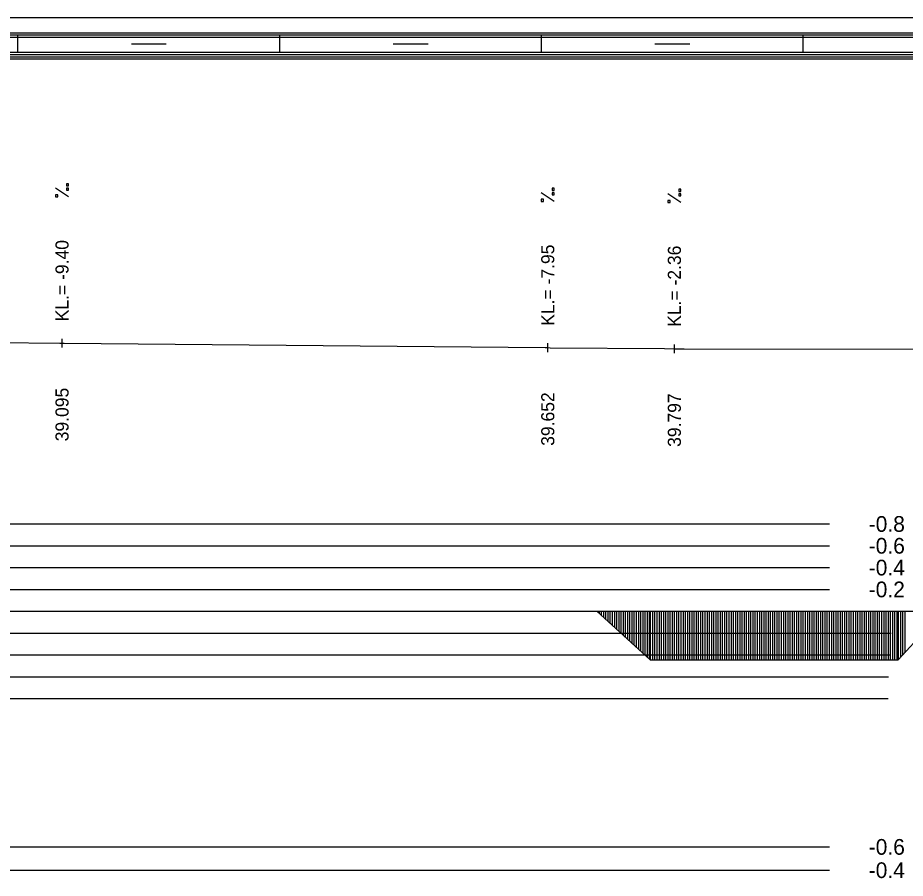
# Model space of a CAD drawing. Extents: x 2 to 10148, y 0 to 380.
# Drawn here: x 4205 to 4306.7, y 281.4 to 380 of the extents above; entities that cross this region are included whole.
import ezdxf

# ---------------------------------------------------------------- set-up
doc = ezdxf.new("R2010")
doc.units = 0
for name, color, linetype in [('NIVELETA_CARA', 7, 'Continuous'), ('NIVELETA_TEXT', 7, 'Continuous'), ('RAM', 7, 'Continuous'), ('ZRYCHL_CARA_C', 7, 'Continuous'), ('ZRYCHL_RASTR', 7, 'Continuous'), ('ZRYCHL_TEXT', 7, 'Continuous')]:
    doc.layers.add(name, color=color, linetype=linetype)

msp = doc.modelspace()

# ---------------------------------------------------------------- linework, layer by layer
at = {"layer": 'NIVELETA_CARA'}
for p, q in [((4188.22, 342.95), (4209.81, 342.72)), ((4210.05, 342.22), (4210.05, 343.22)), ((4209.81, 342.72), (4210.05, 342.72)), ((4210.05, 342.72), (4210.3, 342.72)), ((4210.3, 342.72), (4265.43, 342.2)), ((4265.43, 342.2), (4265.72, 342.2)), ((4265.72, 341.7), (4265.72, 342.7)), ((4265.72, 342.2), (4266.01, 342.19)), ((4266.01, 342.19), (4279.11, 342.09)), ((4279.11, 342.09), (4280.23, 342.08)), ((4280.23, 341.58), (4280.23, 342.58)), ((4280.23, 342.08), (4281.35, 342.08)), ((4281.35, 342.08), (4311.18, 342.01))]:
    msp.add_line(p, q, dxfattribs=at)
at = {"layer": 'NIVELETA_TEXT'}
for p, q in [((4210.8, 359.47), (4209.31, 360.46)), ((4210.8, 360.99), (4210.55, 360.99)), ((4210.55, 360.99), (4210.55, 360.74)), ((4210.55, 360.74), (4210.8, 360.74)), ((4210.55, 360.74), (4210.56, 360.74)), ((4210.8, 360.48), (4210.55, 360.48)), ((4210.55, 360.48), (4210.55, 360.23)), ((4210.55, 360.23), (4210.8, 360.23)), ((4210.55, 360.23), (4210.56, 360.23)), ((4210.8, 360.74), (4210.8, 360.99)), ((4210.8, 360.23), (4210.8, 360.48)), ((4266.47, 360.46), (4266.22, 360.46)), ((4266.22, 360.46), (4266.22, 360.22)), ((4266.22, 360.22), (4266.47, 360.22)), ((4266.22, 360.22), (4266.23, 360.22)), ((4266.47, 360.22), (4266.47, 360.46)), ((4280.98, 360.35), (4280.73, 360.35)), ((4280.73, 360.35), (4280.73, 360.11)), ((4280.73, 360.11), (4280.74, 360.1)), ((4280.73, 360.1), (4280.98, 360.1)), ((4280.98, 360.1), (4280.98, 360.35)), ((4209.55, 359.72), (4209.31, 359.72)), ((4209.31, 359.72), (4209.31, 359.48)), ((4209.31, 359.48), (4209.31, 359.47)), ((4209.31, 359.47), (4209.55, 359.47)), ((4209.55, 359.47), (4209.55, 359.72)), ((4266.47, 358.95), (4264.97, 359.94)), ((4265.22, 359.2), (4264.97, 359.2)), ((4264.97, 359.2), (4264.97, 358.95)), ((4265.22, 358.95), (4265.22, 359.2)), ((4266.47, 359.95), (4266.22, 359.95)), ((4266.22, 359.95), (4266.22, 359.71)), ((4266.22, 359.71), (4266.23, 359.7)), ((4266.22, 359.7), (4266.47, 359.7)), ((4266.47, 359.7), (4266.47, 359.95)), ((4280.98, 358.83), (4279.48, 359.82)), ((4279.73, 359.08), (4279.48, 359.08)), ((4279.48, 359.08), (4279.48, 358.84)), ((4279.73, 358.83), (4279.73, 359.08)), ((4280.98, 359.84), (4280.73, 359.84)), ((4280.73, 359.84), (4280.73, 359.59)), ((4280.73, 359.59), (4280.98, 359.59)), ((4280.73, 359.59), (4280.74, 359.59)), ((4280.98, 359.59), (4280.98, 359.84)), ((4264.97, 358.95), (4265.22, 358.95)), ((4264.97, 358.95), (4264.98, 358.95)), ((4279.48, 358.84), (4279.49, 358.83)), ((4279.48, 358.83), (4279.73, 358.83))]:
    msp.add_line(p, q, dxfattribs=at)
at = {"layer": 'RAM'}
for p, q in [((5128.6, 380), (4045.76, 380)), ((5128.6, 378.25), (4045.76, 378.25)), ((5128.6, 378), (4045.76, 378)), ((5128.6, 377.75), (4045.76, 377.75)), ((4205, 376), (4205, 378)), ((4235, 376), (4235, 378)), ((4265, 376), (4265, 378)), ((4295, 376), (4295, 378)), ((4218, 377), (4222, 377)), ((4248, 377), (4252, 377)), ((4278, 377), (4282, 377)), ((5128.6, 376), (4045.76, 376)), ((5128.6, 375.75), (4045.76, 375.75)), ((5128.6, 375.5), (4045.76, 375.5)), ((5128.6, 375.25), (4045.76, 375.25))]:
    msp.add_line(p, q, dxfattribs=at)
at = {"layer": 'ZRYCHL_CARA_C'}
for p, q in [((4045.76, 312), (5128.6, 312)), ((4271.35, 312), (4277.47, 306.42)), ((4271.6, 312), (4271.6, 311.77)), ((4271.85, 312), (4271.85, 311.54)), ((4272.1, 312), (4272.1, 311.32)), ((4272.35, 312), (4272.35, 311.09)), ((4272.6, 312), (4272.6, 310.86)), ((4272.85, 312), (4272.85, 310.63)), ((4273.1, 312), (4273.1, 310.4)), ((4273.35, 312), (4273.35, 310.18)), ((4273.6, 312), (4273.6, 309.95)), ((4273.85, 312), (4273.85, 309.72)), ((4274.1, 312), (4274.1, 309.49)), ((4274.35, 312), (4274.35, 309.26)), ((4274.6, 312), (4274.6, 309.04)), ((4274.85, 312), (4274.85, 308.81)), ((4275.1, 312), (4275.1, 308.58)), ((4275.35, 312), (4275.35, 308.35)), ((4275.6, 312), (4275.6, 308.13)), ((4275.85, 312), (4275.85, 307.9)), ((4276.1, 312), (4276.1, 307.67)), ((4276.35, 312), (4276.35, 307.44)), ((4276.6, 312), (4276.6, 307.21)), ((4276.85, 312), (4276.85, 306.99)), ((4277.1, 312), (4277.1, 306.76)), ((4277.35, 312), (4277.35, 306.53)), ((4277.47, 312), (4277.47, 306.42)), ((4277.72, 312), (4277.72, 306.42)), ((4277.97, 312), (4277.97, 306.42)), ((4278.22, 312), (4278.22, 306.42)), ((4278.47, 312), (4278.47, 306.42)), ((4278.72, 312), (4278.72, 306.42)), ((4278.97, 312), (4278.97, 306.42)), ((4279.22, 312), (4279.22, 306.42)), ((4279.47, 312), (4279.47, 306.42)), ((4279.72, 312), (4279.72, 306.42)), ((4279.97, 312), (4279.97, 306.42)), ((4280.22, 312), (4280.22, 306.42)), ((4280.47, 312), (4280.47, 306.42)), ((4280.72, 312), (4280.72, 306.42)), ((4280.97, 312), (4280.97, 306.42)), ((4281.22, 312), (4281.22, 306.42)), ((4281.47, 312), (4281.47, 306.42)), ((4281.72, 312), (4281.72, 306.42)), ((4281.97, 312), (4281.97, 306.42)), ((4282.22, 312), (4282.22, 306.42)), ((4282.47, 312), (4282.47, 306.42)), ((4282.72, 312), (4282.72, 306.42)), ((4282.97, 312), (4282.97, 306.42)), ((4283.22, 312), (4283.22, 306.42)), ((4283.47, 312), (4283.47, 306.42)), ((4283.72, 312), (4283.72, 306.42)), ((4283.97, 312), (4283.97, 306.42)), ((4284.22, 312), (4284.22, 306.42)), ((4284.47, 312), (4284.47, 306.42)), ((4284.72, 312), (4284.72, 306.42)), ((4284.97, 312), (4284.97, 306.42)), ((4285.22, 312), (4285.22, 306.42)), ((4285.47, 312), (4285.47, 306.42)), ((4285.72, 312), (4285.72, 306.42)), ((4285.97, 312), (4285.97, 306.42)), ((4286.22, 312), (4286.22, 306.42)), ((4286.47, 312), (4286.47, 306.42)), ((4286.72, 312), (4286.72, 306.42)), ((4286.97, 312), (4286.97, 306.42)), ((4287.22, 312), (4287.22, 306.42)), ((4287.47, 312), (4287.47, 306.42)), ((4287.72, 312), (4287.72, 306.42)), ((4287.97, 312), (4287.97, 306.42)), ((4288.22, 312), (4288.22, 306.42)), ((4288.47, 312), (4288.47, 306.42)), ((4288.72, 312), (4288.72, 306.42)), ((4288.97, 312), (4288.97, 306.42)), ((4289.22, 312), (4289.22, 306.42)), ((4289.47, 312), (4289.47, 306.42)), ((4289.72, 312), (4289.72, 306.42)), ((4289.97, 312), (4289.97, 306.42)), ((4290.22, 312), (4290.22, 306.42)), ((4290.47, 312), (4290.47, 306.42)), ((4290.72, 312), (4290.72, 306.42)), ((4290.97, 312), (4290.97, 306.42)), ((4291.22, 312), (4291.22, 306.42)), ((4291.47, 312), (4291.47, 306.42)), ((4291.72, 312), (4291.72, 306.42)), ((4291.97, 312), (4291.97, 306.42)), ((4292.22, 312), (4292.22, 306.42)), ((4292.47, 312), (4292.47, 306.42)), ((4292.72, 312), (4292.72, 306.42)), ((4292.97, 312), (4292.97, 306.42)), ((4293.22, 312), (4293.22, 306.42)), ((4293.47, 312), (4293.47, 306.42)), ((4293.72, 312), (4293.72, 306.42)), ((4293.97, 312), (4293.97, 306.42)), ((4294.22, 312), (4294.22, 306.42)), ((4294.47, 312), (4294.47, 306.42)), ((4294.72, 312), (4294.72, 306.42)), ((4294.97, 312), (4294.97, 306.42)), ((4295.22, 312), (4295.22, 306.42)), ((4295.47, 312), (4295.47, 306.42)), ((4295.72, 312), (4295.72, 306.42)), ((4295.97, 312), (4295.97, 306.42)), ((4296.22, 312), (4296.22, 306.42)), ((4296.47, 312), (4296.47, 306.42)), ((4296.72, 312), (4296.72, 306.42)), ((4296.97, 312), (4296.97, 306.42)), ((4297.22, 312), (4297.22, 306.42)), ((4297.47, 312), (4297.47, 306.42)), ((4297.72, 312), (4297.72, 306.42)), ((4297.97, 312), (4297.97, 306.42)), ((4298.22, 312), (4298.22, 306.42)), ((4298.47, 312), (4298.47, 306.42)), ((4298.72, 312), (4298.72, 306.42)), ((4298.97, 312), (4298.97, 306.42)), ((4299.22, 312), (4299.22, 306.42)), ((4299.47, 312), (4299.47, 306.42)), ((4299.72, 312), (4299.72, 306.42)), ((4299.97, 312), (4299.97, 306.42)), ((4300.22, 312), (4300.22, 306.42)), ((4300.47, 312), (4300.47, 306.42)), ((4300.72, 312), (4300.72, 306.42)), ((4300.97, 312), (4300.97, 306.42)), ((4301.22, 312), (4301.22, 306.42)), ((4301.47, 312), (4301.47, 306.42)), ((4301.72, 312), (4301.72, 306.42)), ((4301.97, 312), (4301.97, 306.42)), ((4302.22, 312), (4302.22, 306.42)), ((4302.47, 312), (4302.47, 306.42)), ((4302.72, 312), (4302.72, 306.42)), ((4302.97, 312), (4302.97, 306.42)), ((4303.22, 312), (4303.22, 306.42)), ((4303.47, 312), (4303.47, 306.42)), ((4303.72, 312), (4303.72, 306.42)), ((4303.97, 312), (4303.97, 306.42)), ((4304.22, 312), (4304.22, 306.42)), ((4304.47, 312), (4304.47, 306.42)), ((4304.72, 312), (4304.72, 306.42)), ((4304.97, 312), (4304.97, 306.42)), ((4305.22, 312), (4305.22, 306.42)), ((4305.47, 312), (4305.47, 306.42)), ((4305.72, 312), (4305.72, 306.42)), ((4305.88, 312), (4305.88, 306.42)), ((4305.88, 306.42), (4310.99, 312)), ((4306.13, 312), (4306.13, 306.69)), ((4306.38, 312), (4306.38, 306.97)), ((4306.63, 312), (4306.63, 307.24)), ((4277.47, 306.42), (4305.88, 306.42))]:
    msp.add_line(p, q, dxfattribs=at)
at = {"layer": 'ZRYCHL_RASTR'}
for p, q in [((4102, 322), (4298, 322)), ((4102, 319.5), (4298, 319.5)), ((4102, 317), (4298, 317)), ((4102, 314.5), (4298, 314.5)), ((4102, 309.5), (4305.06, 309.5)), ((4102, 307), (4305.01, 307)), ((4102, 304.5), (4304.78, 304.5)), ((4102, 302), (4304.73, 302)), ((4102, 285), (4298, 285)), ((4102, 282.33), (4298, 282.33))]:
    msp.add_line(p, q, dxfattribs=at)

# ---------------------------------------------------------------- texts
at = {"layer": 'NIVELETA_TEXT'}
for s, p in [('KL.= -9.40', (4210.8, 345.22)), ('KL.= -7.95', (4266.47, 344.7)), ('KL.= -2.36', (4280.98, 344.58)), ('39.095', (4210.8, 331.47)), ('39.652', (4266.47, 330.95)), ('39.797', (4280.98, 330.83))]:
    msp.add_text(s, height=1.5, rotation=90, dxfattribs=at).set_placement(p)
at = {"layer": 'ZRYCHL_TEXT'}
for s, p in [('-0.8', (4302.5, 321.1)), ('-0.6', (4302.5, 318.6)), ('-0.4', (4302.5, 316.1)), ('-0.2', (4302.5, 313.6)), ('-0.6', (4302.5, 284.1)), ('-0.4', (4302.5, 281.43))]:
    msp.add_text(s, height=1.8, dxfattribs=at).set_placement(p)

doc.saveas('drawing.dxf')
